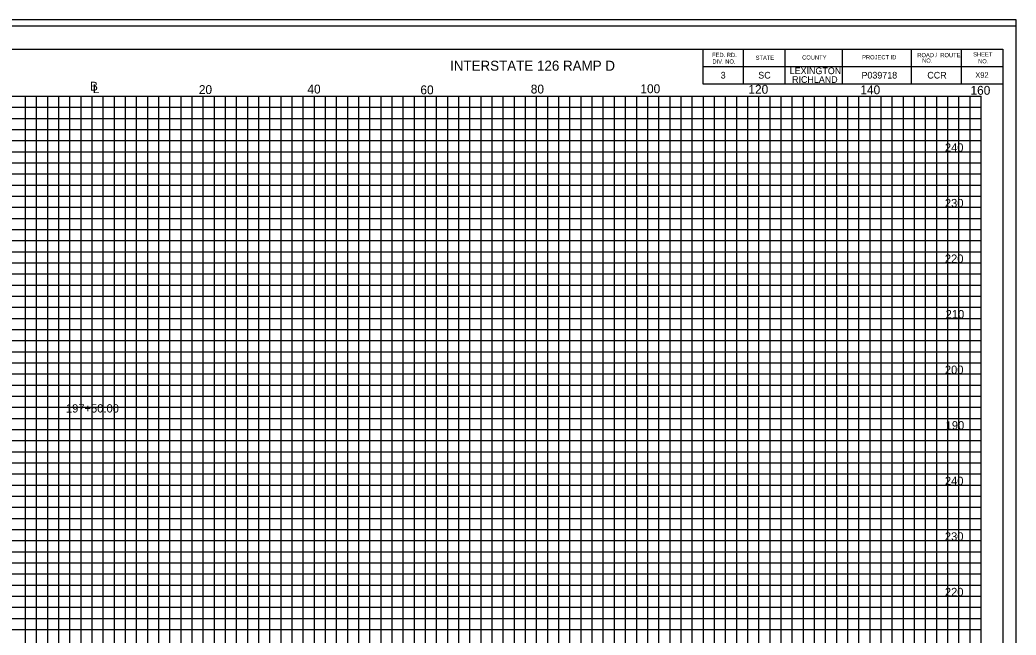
# Model space of a CAD drawing. Extents: x 967 to 1326, y 964 to 2304.
# Drawn here: x 1147 to 1326.3, y 1353 to 1463.7 of the extents above; entities that cross this region are included whole.
import ezdxf

# ---------------------------------------------------------------- set-up
doc = ezdxf.new("R2010")
doc.units = 0
for name, color, linetype in [('Default', 7, 'Continuous'), ('RD_GPK_XS_Cell', 7, 'Continuous'), ('RD_PD_PaveShd', 7, 'Continuous'), ('RD_XS_ExGround', 7, 'Continuous'), ('RD_XS_ExPaveRet', 7, 'Continuous'), ('RD_XS_PaveOvlay', 7, 'Continuous'), ('RD_XS_TX_Elev_EX', 7, 'Continuous')]:
    doc.layers.add(name, color=color, linetype=linetype)

msp = doc.modelspace()

# ---------------------------------------------------------------- linework, layer by layer
at = {"layer": 'RD_GPK_XS_Cell'}
for p, q in [((1000, 1450), (1320, 1450)), ((1150, 1280), (1150, 1450)), ((1160, 1280), (1160, 1450)), ((1170, 1280), (1170, 1450)), ((1180, 1280), (1180, 1450)), ((1190, 1280), (1190, 1450)), ((1200, 1280), (1200, 1450)), ((1210, 1280), (1210, 1450)), ((1220, 1280), (1220, 1450)), ((1230, 1280), (1230, 1450)), ((1240, 1280), (1240, 1450)), ((1250, 1280), (1250, 1450)), ((1260, 1280), (1260, 1450)), ((1270, 1280), (1270, 1450)), ((1280, 1280), (1280, 1450)), ((1290, 1280), (1290, 1450)), ((1300, 1280), (1300, 1450)), ((1310, 1280), (1310, 1450)), ((1320, 1280), (1320, 1450)), ((1000, 1440), (1320, 1440)), ((1000, 1430), (1320, 1430)), ((1000, 1420), (1320, 1420)), ((1000, 1410), (1320, 1410)), ((1000, 1400), (1320, 1400)), ((1000, 1390), (1320, 1390)), ((1000, 1380), (1320, 1380)), ((1000, 1370), (1320, 1370)), ((1000, 1360), (1320, 1360))]:
    msp.add_line(p, q, dxfattribs=at)
at = {"layer": 'RD_PD_PaveShd'}
for p, q in [((996.11, 1458.46), (1323.89, 1458.46)), ((1269.89, 1458.46), (1269.89, 1452.21)), ((1277.14, 1458.46), (1277.14, 1452.21)), ((1284.64, 1458.46), (1284.64, 1452.21)), ((1295, 1458.46), (1295, 1452.21)), ((1307.43, 1458.46), (1307.43, 1452.21)), ((1316.39, 1458.46), (1316.39, 1452.21)), ((1323.89, 1458.46), (1323.89, 1248.98)), ((1269.89, 1455.33), (1323.89, 1455.33)), ((1269.89, 1452.21), (1323.89, 1452.21))]:
    msp.add_line(p, q, dxfattribs=at)
at = {"layer": 'RD_XS_ExGround'}
for p, q in [((1148, 1280), (1148, 1450)), ((1152, 1280), (1152, 1450)), ((1154, 1280), (1154, 1450)), ((1156, 1280), (1156, 1450)), ((1158, 1280), (1158, 1450)), ((1162, 1280), (1162, 1450)), ((1164, 1280), (1164, 1450)), ((1166, 1280), (1166, 1450)), ((1168, 1280), (1168, 1450)), ((1172, 1280), (1172, 1450)), ((1174, 1280), (1174, 1450)), ((1176, 1280), (1176, 1450)), ((1178, 1280), (1178, 1450)), ((1182, 1280), (1182, 1450)), ((1184, 1280), (1184, 1450)), ((1186, 1280), (1186, 1450)), ((1188, 1280), (1188, 1450)), ((1192, 1280), (1192, 1450)), ((1194, 1280), (1194, 1450)), ((1196, 1280), (1196, 1450)), ((1198, 1280), (1198, 1450)), ((1202, 1280), (1202, 1450)), ((1204, 1280), (1204, 1450)), ((1206, 1280), (1206, 1450)), ((1208, 1280), (1208, 1450)), ((1212, 1280), (1212, 1450)), ((1214, 1280), (1214, 1450)), ((1216, 1280), (1216, 1450)), ((1218, 1280), (1218, 1450)), ((1222, 1280), (1222, 1450)), ((1224, 1280), (1224, 1450)), ((1226, 1280), (1226, 1450)), ((1228, 1280), (1228, 1450)), ((1232, 1280), (1232, 1450)), ((1234, 1280), (1234, 1450)), ((1236, 1280), (1236, 1450)), ((1238, 1280), (1238, 1450)), ((1242, 1280), (1242, 1450)), ((1244, 1280), (1244, 1450)), ((1246, 1280), (1246, 1450)), ((1248, 1280), (1248, 1450)), ((1252, 1280), (1252, 1450)), ((1254, 1280), (1254, 1450)), ((1256, 1280), (1256, 1450)), ((1258, 1280), (1258, 1450)), ((1262, 1280), (1262, 1450)), ((1264, 1280), (1264, 1450)), ((1266, 1280), (1266, 1450)), ((1268, 1280), (1268, 1450)), ((1272, 1280), (1272, 1450)), ((1274, 1280), (1274, 1450)), ((1276, 1280), (1276, 1450)), ((1278, 1280), (1278, 1450)), ((1282, 1280), (1282, 1450)), ((1284, 1280), (1284, 1450)), ((1286, 1280), (1286, 1450)), ((1288, 1280), (1288, 1450)), ((1292, 1280), (1292, 1450)), ((1294, 1280), (1294, 1450)), ((1296, 1280), (1296, 1450)), ((1298, 1280), (1298, 1450)), ((1302, 1280), (1302, 1450)), ((1304, 1280), (1304, 1450)), ((1306, 1280), (1306, 1450)), ((1308, 1280), (1308, 1450)), ((1312, 1280), (1312, 1450)), ((1314, 1280), (1314, 1450)), ((1316, 1280), (1316, 1450)), ((1318, 1280), (1318, 1450)), ((1000, 1448), (1320, 1448)), ((1000, 1446), (1320, 1446)), ((1000, 1444), (1320, 1444)), ((1000, 1442), (1320, 1442)), ((1000, 1438), (1320, 1438)), ((1000, 1436), (1320, 1436)), ((1000, 1434), (1320, 1434)), ((1000, 1432), (1320, 1432)), ((1000, 1428), (1320, 1428)), ((1000, 1426), (1320, 1426)), ((1000, 1424), (1320, 1424)), ((1000, 1422), (1320, 1422)), ((1000, 1418), (1320, 1418)), ((1000, 1416), (1320, 1416)), ((1000, 1414), (1320, 1414)), ((1000, 1412), (1320, 1412)), ((1000, 1408), (1320, 1408)), ((1000, 1406), (1320, 1406)), ((1000, 1404), (1320, 1404)), ((1000, 1402), (1320, 1402)), ((1000, 1398), (1320, 1398)), ((1000, 1396), (1320, 1396)), ((1000, 1394), (1320, 1394)), ((1000, 1392), (1320, 1392)), ((1000, 1388), (1320, 1388)), ((1000, 1386), (1320, 1386)), ((1000, 1384), (1320, 1384)), ((1000, 1382), (1320, 1382)), ((1000, 1378), (1320, 1378)), ((1000, 1376), (1320, 1376)), ((1000, 1374), (1320, 1374)), ((1000, 1372), (1320, 1372)), ((1000, 1368), (1320, 1368)), ((1000, 1366), (1320, 1366)), ((1000, 1364), (1320, 1364)), ((1000, 1362), (1320, 1362)), ((1000, 1358), (1320, 1358)), ((1000, 1356), (1320, 1356)), ((1000, 1354), (1320, 1354))]:
    msp.add_line(p, q, dxfattribs=at)
at = {"layer": 'RD_XS_PaveOvlay'}
msp.add_lwpolyline([(967.41, 1243.72), (1326.28, 1243.72), (1326.28, 1463.72), (967.41, 1463.72)], close=True, dxfattribs=at)
at = {"layer": 'RD_XS_TX_Elev_EX'}
for points in [[(967.41, 1243.72), (1326.28, 1243.72), (1326.28, 1463.72), (967.41, 1463.72)], [(988.52, 1244.84), (1326.28, 1244.84), (1326.28, 1462.6), (988.52, 1462.6)]]:
    msp.add_lwpolyline(points, close=True, dxfattribs=at)

# ---------------------------------------------------------------- texts
at = {"layer": 'Default'}
for s, height, p in [('X92', 1, (1318.95, 1453.3)), ('240', 1.5, (1313.47, 1440)), ('230', 1.5, (1313.47, 1430)), ('220', 1.5, (1313.47, 1420)), ('210', 1.5, (1313.61, 1410)), ('200', 1.5, (1313.47, 1400)), ('197+50.00', 1.5, (1155.28, 1393.05)), ('190', 1.5, (1313.61, 1390)), ('240', 1.5, (1313.47, 1380)), ('230', 1.5, (1313.47, 1370)), ('220', 1.5, (1313.47, 1360))]:
    msp.add_text(s, height=height, dxfattribs=at).set_placement(p)
at = {"layer": 'RD_XS_ExPaveRet'}
for s, height, p in [('FED. RD.', 0.75, (1271.58, 1457.05)), ('ROAD /  ROUTE', 0.75, (1308.51, 1457.01)), ('SHEET', 0.75, (1318.56, 1457.16)), ('DIV. NO.', 0.75, (1271.64, 1455.86)), ('STATE', 0.75, (1279.41, 1456.53)), ('COUNTY', 0.75, (1287.78, 1456.59)), ('PROJECT ID', 0.75, (1298.58, 1456.63)), ('   NO.', 0.75, (1308.51, 1456.03)), ('NO.', 0.75, (1319.45, 1455.91)), ('3', 1.2, (1273.12, 1453.17)), ('SC', 1.2, (1279.89, 1453.17)), ('LEXINGTON', 1.2, (1285.54, 1453.96)), ('P039718', 1.2, (1298.46, 1453.17)), ('CCR', 1.2, (1310.31, 1453.17)), ('B', 1.6, (1159.61, 1450.99)), ('RICHLAND', 1.2, (1285.97, 1452.39)), ('L', 1.6, (1160.12, 1450.54)), ('20', 1.6, (1179.2, 1450.38)), ('40', 1.6, (1198.74, 1450.47)), ('60', 1.6, (1219.08, 1450.33)), ('80', 1.6, (1238.94, 1450.47)), ('100', 1.6, (1258.67, 1450.53)), ('120', 1.6, (1278.11, 1450.43)), ('140', 1.6, (1298.26, 1450.34)), ('160', 1.6, (1318.08, 1450.25))]:
    msp.add_text(s, height=height, dxfattribs=at).set_placement(p)
msp.add_text('INTERSTATE 126 RAMP D', height=1.8, rotation=0, dxfattribs=at).set_placement((1224.41, 1454.58))

doc.saveas('drawing.dxf')
